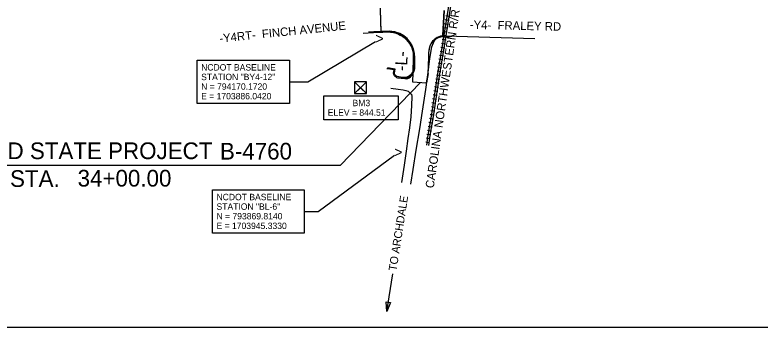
# Model space of a CAD drawing. Extents: x 1701144 to 1707001, y 793349 to 797175.
# Drawn here: x 1702973 to 1704835, y 793436 to 794216 of the extents above; entities that cross this region are included whole.
import ezdxf

# ---------------------------------------------------------------- set-up
doc = ezdxf.new("R2010")
doc.units = 0
for name, color, linetype in [('CTL Sheet Border CELL', 7, 'Continuous'), ('CTL Sheet Text', 7, 'Continuous'), ('Default', 7, 'Continuous'), ('Exist Property Titlesheet Border PSD CELL', 7, 'Continuous'), ('Old_Level_3', 7, 'Continuous'), ('Old_Level_5', 7, 'Continuous'), ('Old_Level_57', 7, 'Continuous'), ('Prop EOT', 7, 'Continuous'), ('Proposed Right of Way Monument PSD Leader', 7, 'Continuous'), ('Proposed Right of Way Monument PSD Text', 7, 'Continuous'), ('Sheet Title CELL', 7, 'Continuous')]:
    doc.layers.add(name, color=color, linetype=linetype)

msp = doc.modelspace()

# ---------------------------------------------------------------- linework, layer by layer
at = {"layer": 'CTL Sheet Border CELL'}
msp.add_lwpolyline([(1706942.2, 797087.9), (1701724.8, 797087.9), (1701724.8, 793435.7), (1706942.2, 793435.7)], close=True, dxfattribs=at)
at = {"layer": 'CTL Sheet Text'}
for p, q in [((1703785.7, 793839.9), (1703986.1, 794047.4)), ((1703785.7, 793839.9), (1702843.1, 793839.9)), ((1703902.6, 793474.6), (1703917.4, 793569))]:
    msp.add_line(p, q, dxfattribs=at)
msp.add_lwpolyline([(1703901.1, 793499.3), (1703911.6, 793497.6), (1703902.6, 793474.6)], close=True, dxfattribs=at)
at = {"layer": 'Default'}
for p, q in [((1703885.6, 794230.3), (1703886.4, 794202.2)), ((1704041.9, 794164.4), (1704045.6, 794227.2)), ((1703887.1, 794175.5), (1703912.9, 794174.7)), ((1704041.9, 794163.8), (1704041.9, 794164.4)), ((1704041.9, 794164.4), (1704041.9, 794164.4)), ((1704041.9, 794164.4), (1704041.9, 794164.4)), ((1703967.7, 794071.4), (1703966.7, 794048.9)), ((1704001.8, 794046.2), (1704005.6, 794069.4)), ((1704005.6, 794069.4), (1704005.6, 794069.4)), ((1703966.7, 794048.9), (1704001.8, 794046.2))]:
    msp.add_line(p, q, dxfattribs=at)
msp.add_lwpolyline([(1703886.4, 794202.2), (1703886.5, 794197.2), (1703887.1, 794175.5)], dxfattribs=at)
msp.add_lwpolyline([(1703744.6, 794013.9), (1703930.4, 794013.9), (1703930.4, 793953.9), (1703744.6, 793953.9)], close=True, dxfattribs=at)
for centre, radius, start, end in [((1703911.1, 794116.7), 58, 359.5057, 88.2385), ((1704047.1, 794124.2), 40, 97.5132, 179.9743), ((1702989.1, 794124.6), 1018, 356.8874, 359.9743), ((1702989.1, 794124.6), 980, 356.8874, 359.5057)]:
    msp.add_arc(centre, radius, start, end, dxfattribs=at)
at = {"layer": 'Exist Property Titlesheet Border PSD CELL'}
for points in [[(1703428.5, 794103), (1703659.4, 794103), (1703659.4, 793995), (1703428.5, 793995)], [(1703466.9, 793778.9), (1703695.8, 793778.9), (1703695.8, 793670.9), (1703466.9, 793670.9)]]:
    msp.add_lwpolyline(points, close=True, dxfattribs=at)
at = {"layer": 'Old_Level_3'}
msp.add_line((1704103.7, 794161.9), (1704272, 794156.7), dxfattribs=at)
for points in [[(1703856.7, 794173.7), (1703869.5, 794174.3), (1703887.6, 794175.5), (1703899.7, 794175.8), (1703908.8, 794175.9), (1703914.7, 794175.4), (1703921.2, 794174.3), (1703928.4, 794171.9), (1703934.7, 794169.2), (1703940.2, 794166.1), (1703945.8, 794162.2), (1703950.4, 794158.3), (1703955.7, 794152.7), (1703960.6, 794146.3), (1703964.5, 794139.5), (1703968.1, 794131.5), (1703969.4, 794127.4), (1703971, 794119.2), (1703971.6, 794109.3), (1703971.6, 794094.2), (1703971.2, 794082.4), (1703970.8, 794078.2), (1703970.2, 794075.6), (1703968.2, 794071.3), (1703966.6, 794068.2), (1703964.6, 794065.4)], [(1703843.1, 794170.5), (1703868.9, 794172.2), (1703892.5, 794173.2), (1703904.6, 794173.7), (1703911.8, 794173.3), (1703918.7, 794172.2), (1703925.9, 794170.1), (1703931.3, 794168.2), (1703936, 794165.6), (1703942, 794162), (1703946, 794159.2), (1703950.2, 794155.6), (1703956, 794148.8), (1703959.1, 794144.4), (1703962.2, 794139.1), (1703964.7, 794133.8), (1703966.8, 794128.2), (1703968.3, 794121.8), (1703969.4, 794113.4), (1703969.2, 794096.3), (1703968.9, 794084), (1703968, 794076.5), (1703966.1, 794072.7), (1703962.8, 794067.2), (1703958.8, 794063.9), (1703954.3, 794061.4), (1703950.6, 794059.9), (1703946.3, 794059.4), (1703941.5, 794059.3), (1703927.7, 794061.8), (1703924.7, 794063.8), (1703922.2, 794066.7), (1703921.3, 794070.7), (1703922.8, 794080.8), (1703904.2, 794083.6)], [(1703962.7, 793793.2), (1703968.4, 793829.9), (1703975.8, 793878.2), (1703984.4, 793931.3), (1703991.5, 793975.3), (1703999.4, 794029.2), (1704005.5, 794072.4), (1704009.6, 794106.9), (1704014.9, 794136.4), (1704018.8, 794146.2), (1704022.6, 794152.6), (1704026.6, 794156.7), (1704031.6, 794159.7), (1704037, 794161.4), (1704042.3, 794162), (1704045.8, 794161.5)], [(1704045.8, 794161.5), (1704047.6, 794161.3)], [(1704047.6, 794161.3), (1704051.8, 794160.7), (1704058, 794161.3), (1704065, 794162.8), (1704075.7, 794163.7)], [(1703964.6, 794065.4), (1703961.2, 794062.5), (1703957.2, 794060), (1703953.8, 794058.5), (1703950.7, 794057.5), (1703946.9, 794056.8), (1703941.9, 794057), (1703933.9, 794058), (1703927.4, 794059.1), (1703925.3, 794060.2), (1703923.2, 794061.7), (1703921.7, 794063.5), (1703920.3, 794065.3), (1703919.5, 794067.2), (1703919, 794070.4), (1703920.3, 794079), (1703903.8, 794081.1), (1703902.2, 794081.3)], [(1703912.2, 794032.9), (1703931, 794030.3), (1703942.9, 794028.8), (1703949.8, 794027.5), (1703955.5, 794025.3), (1703958.3, 794023.2), (1703961.9, 794019.9), (1703964.3, 794017.7)], [(1703964.3, 794017.7), (1703964.8, 794011.8), (1703964.3, 793989.5), (1703962.3, 793961.6), (1703958.9, 793933.4), (1703954.9, 793907.1), (1703950.3, 793875.5)], [(1703950.3, 793875.5), (1703945.7, 793840.4), (1703939.1, 793796.9)]]:
    msp.add_lwpolyline(points, dxfattribs=at)
at = {"layer": 'Old_Level_5'}
for p, q in [((1704059.6, 794212.2), (1704049.8, 794213.7)), ((1704056.5, 794192.4), (1704046.6, 794194)), ((1704058.1, 794202.3), (1704048.2, 794203.9)), ((1704054.9, 794182.5), (1704045, 794184.1)), ((1704051.8, 794162.8), (1704041.9, 794164.4)), ((1704053.3, 794172.7), (1704043.5, 794174.2)), ((1704048.6, 794143), (1704038.8, 794144.6)), ((1704050.2, 794152.9), (1704040.3, 794154.5)), ((1704045.5, 794123.3), (1704035.6, 794124.9)), ((1704047.1, 794133.2), (1704037.2, 794134.7)), ((1704042.3, 794103.5), (1704032.5, 794105.1)), ((1704043.9, 794113.4), (1704034, 794115)), ((1704039.2, 794083.8), (1704029.3, 794085.4)), ((1704040.8, 794093.7), (1704030.9, 794095.2)), ((1704036.1, 794064), (1704026.2, 794065.6)), ((1704037.6, 794073.9), (1704027.8, 794075.5)), ((1704032.9, 794044.3), (1704023, 794045.9)), ((1704034.5, 794054.2), (1704024.6, 794055.7)), ((1704029.8, 794024.5), (1704019.9, 794026.1)), ((1704031.3, 794034.4), (1704021.5, 794036)), ((1704028.2, 794014.7), (1704018.3, 794016.2)), ((1704025, 793994.9), (1704015.2, 793996.5)), ((1704026.6, 794004.8), (1704016.7, 794006.4)), ((1704021.9, 793975.2), (1704012, 793976.7)), ((1704023.5, 793985), (1704013.6, 793986.6)), ((1704018.8, 793955.4), (1704008.9, 793957)), ((1704020.3, 793965.3), (1704010.5, 793966.8)), ((1704015.6, 793935.7), (1704005.7, 793937.2)), ((1704017.2, 793945.5), (1704007.3, 793947.1)), ((1704012.5, 793915.9), (1704002.6, 793917.5)), ((1704014, 793925.8), (1704004.2, 793927.3)), ((1704009.3, 793896.1), (1703999.5, 793897.7)), ((1704010.9, 793906), (1704001, 793907.6))]:
    msp.add_line(p, q, dxfattribs=at)
for points in [[(1704075, 794356.5), (1704067.8, 794311.2), (1704055.3, 794233.1), (1704038.7, 794129), (1704030.1, 794074.8)], [(1704080, 794355.8), (1704072.7, 794310.4), (1704060.2, 794232.3), (1704043.6, 794128.2), (1704035, 794074)], [(1704030, 794074.7), (1704013.6, 793968), (1704005.2, 793915.1), (1704001.4, 793890.6)], [(1704034.9, 794074), (1704018.6, 793967.3), (1704010.2, 793914.3), (1704006.3, 793889.9)]]:
    msp.add_lwpolyline(points, dxfattribs=at)
at = {"layer": 'Old_Level_57'}
for p, q in [((1703821.7, 794048.9), (1703851.2, 794019.4)), ((1703851.2, 794048.9), (1703821.7, 794019.4))]:
    msp.add_line(p, q, dxfattribs=at)
msp.add_lwpolyline([(1703821.7, 794019.4), (1703851.2, 794019.4), (1703851.2, 794048.9), (1703821.7, 794048.9)], close=True, dxfattribs=at)
for points in [[(1703836.4, 794034.1), (1703851.2, 794048.9), (1703821.7, 794048.9), (1703836.4, 794034.1)], [(1703836.4, 794034.1), (1703821.7, 794019.4), (1703851.2, 794019.4), (1703836.4, 794034.1)]]:
    msp.add_lwpolyline(points, dxfattribs=at)
at = {"layer": 'Prop EOT'}
for p, q in [((1703885.6, 794232.7), (1703886.5, 794197.2)), ((1704045.6, 794227.2), (1704041.9, 794163.8)), ((1703886.4, 794202.2), (1703887.1, 794175.5)), ((1703887.1, 794175.5), (1703912.9, 794174.7)), ((1704048.7, 794164.1), (1704103.7, 794161.9)), ((1703967.7, 794071.4), (1703966.4, 794049)), ((1704005.6, 794069.4), (1704001.8, 794046.2)), ((1703928.8, 794058.7), (1703946.5, 794056.8)), ((1703966.7, 794048.9), (1704001.8, 794046.2))]:
    msp.add_line(p, q, dxfattribs=at)
for centre, radius, start, end in [((1703911.1, 794116.7), 58, 359.5057, 88.2385), ((1704047.1, 794124.2), 40, 87.7131, 179.9743), ((1702989.1, 794124.6), 1018, 356.8874, 359.9743), ((1702989.1, 794124.6), 980, 356.8874, 359.5057), ((1703949.8, 794074.6), 18, 264.0066, 357.0156)]:
    msp.add_arc(centre, radius, start, end, dxfattribs=at)
at = {"layer": 'Proposed Right of Way Monument PSD Leader'}
for points in [[(1703659.4, 794049), (1703704.8, 794049), (1703873.8, 794149.4)], [(1703695.8, 793724.9), (1703730.5, 793724.9), (1703921.6, 793865.5)]]:
    msp.add_lwpolyline(points, dxfattribs=at)

# ---------------------------------------------------------------- texts
at = {"layer": 'CTL Sheet Text'}
for s, height, rotation, p in [('END STATE PROJECT ', 41.737, 360, (1702877.4, 793855.6)), ('-L- STA. ', 41.74, 360, (1702877.4, 793786.1)), ('TO ARCHDALE', 20, 81.0805, (1703926.3, 793574.9))]:
    msp.add_text(s, height=height, rotation=rotation, dxfattribs=at).set_placement(p)
for s, p in [('B-4760  ', (1703485.5, 793854.5)), ('34+00.00', (1703129.9, 793787))]:
    msp.add_text(s, height=41.74, dxfattribs=at).set_placement(p)
at = {"layer": 'Old_Level_57'}
for p in [(1703873.9, 794144.2), (1703920.7, 793860.1)]:
    msp.add_text('>', height=26.1, rotation=0.0142, dxfattribs=at).set_placement(p)
at = {"layer": 'Proposed Right of Way Monument PSD Text'}
for s, p in [('NCDOT BASELINE', (1703438.5, 794077)), ('STATION "BY4-12"', (1703438.5, 794053)), ('N = 794170.1720', (1703438.5, 794029)), ('E = 1703886.0420', (1703438.5, 794005)), ('BM3', (1703816.8, 793987.9)), ('ELEV = 844.51', (1703754.6, 793963.9)), ('NCDOT BASELINE', (1703476.9, 793752.9)), ('STATION "BL-6"', (1703476.9, 793728.9)), ('N = 793869.8140', (1703476.9, 793704.9)), ('E = 1703945.3330', (1703476.9, 793680.9))]:
    msp.add_text(s, height=16, dxfattribs=at).set_placement(p)
at = {"layer": 'Sheet Title CELL'}
for s, height, rotation, p in [('CAROLINA NORTHWESTERN R/R', 21.157, 81.6993, (1704019.4, 793781.8)), ('-Y4RT-  FINCH AVENUE', 21.157, 5.9331, (1703485.1, 794146.6)), ('-Y4-  FRALEY RD', 21.157, 358.7619, (1704109.7, 794181.2)), ('-L-', 30, 87.0188, (1703952.4, 794075.5))]:
    msp.add_text(s, height=height, rotation=rotation, dxfattribs=at).set_placement(p)

doc.saveas('drawing.dxf')
